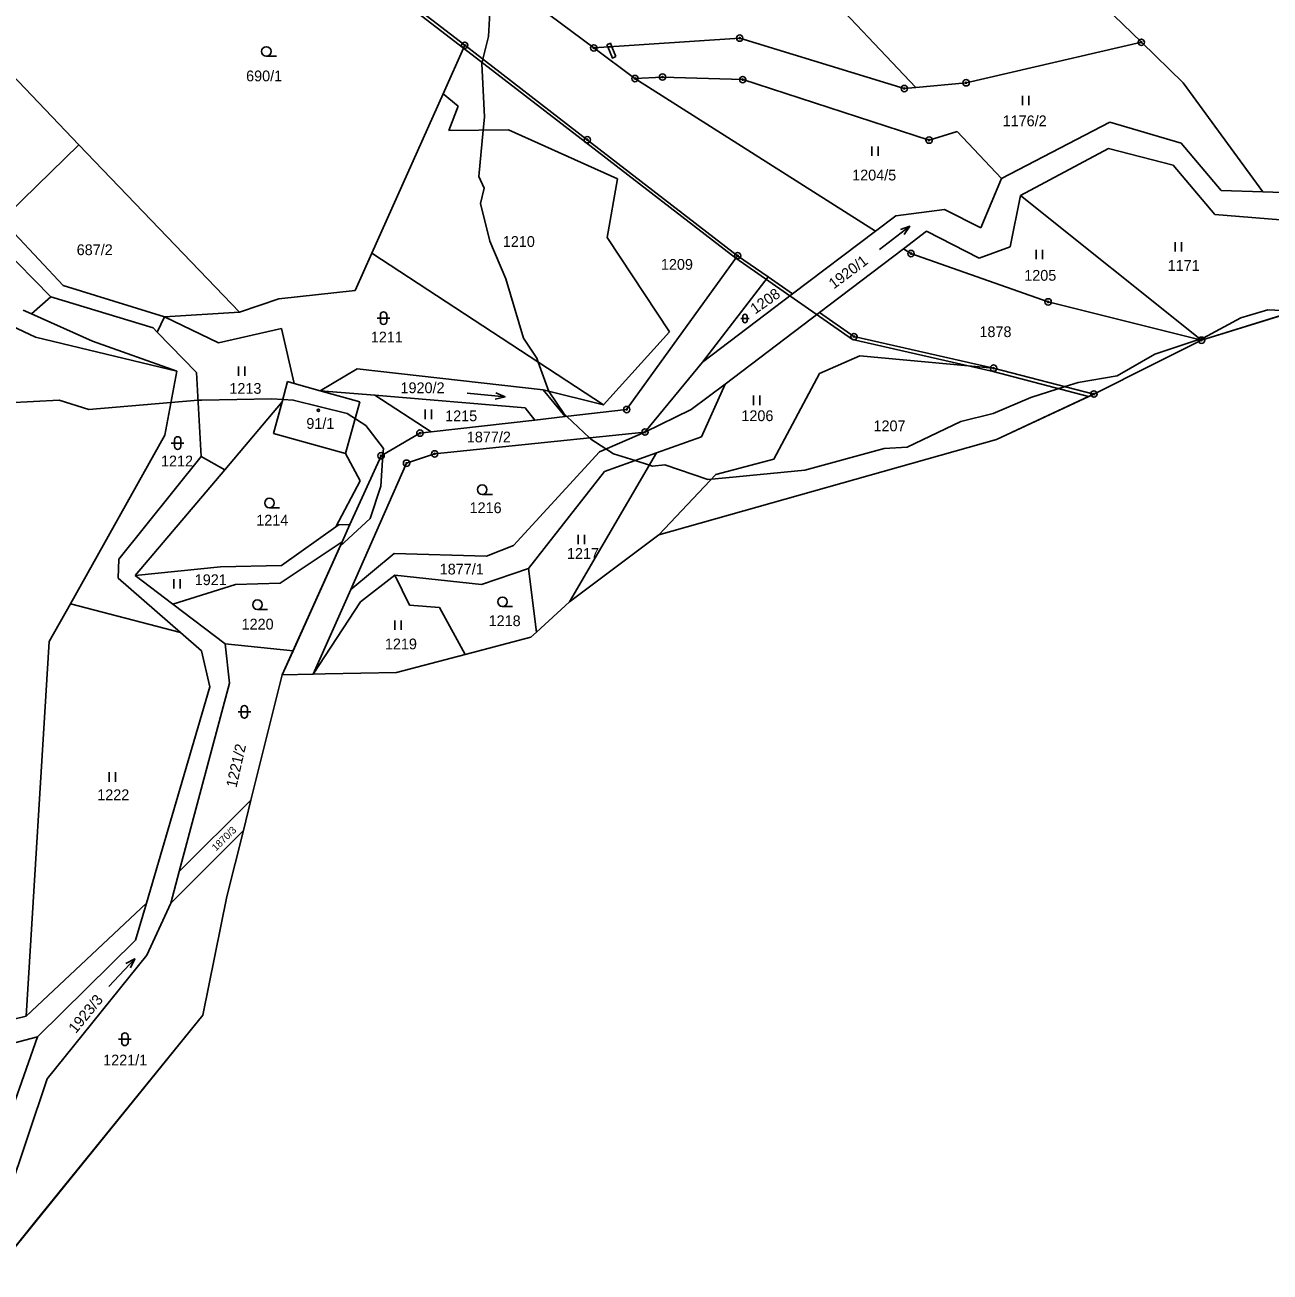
# Model space of a CAD drawing. Extents: x -445050 to -440454, y -1134563 to -1129741.
# Drawn here: x -441360.7 to -441164.1, y -1132219.4 to -1132022.5 of the extents above; entities that cross this region are included whole.
import ezdxf

# ---------------------------------------------------------------- set-up
doc = ezdxf.new("R2010")
doc.units = 0
for name, color, linetype in [('Vrstva 1', 7, 'Continuous'), ('Vrstva 13', 7, 'Continuous'), ('Vrstva 16', 7, 'Continuous'), ('Vrstva 18', 7, 'Continuous'), ('Vrstva 19', 7, 'Continuous'), ('Vrstva 24', 7, 'Continuous'), ('Vrstva 25', 7, 'Continuous'), ('Vrstva 3', 7, 'Continuous'), ('Vrstva 30', 7, 'Continuous'), ('Vrstva 37', 7, 'Continuous'), ('Vrstva 4', 7, 'Continuous'), ('Vrstva 5', 7, 'Continuous'), ('Vrstva 52', 7, 'Continuous')]:
    doc.layers.add(name, color=color, linetype=linetype)

msp = doc.modelspace()

# ---------------------------------------------------------------- linework, layer by layer
at = {"layer": 'Vrstva 1'}
for points in [[(-441291.24, -1132025.75), (-441326.34, -1131998.71)], [(-441210.7, -1131999.85), (-441184.4, -1132025.27)], [(-441298.88, -1132005.29), (-441270.86, -1132026.16)], [(-441352.15, -1132041.44), (-441384.04, -1132008.03)], [(-441220.04, -1132032.4), (-441235.94, -1132015.52)], [(-441247.82, -1132024.61), (-441270.86, -1132026.16)], [(-441221.84, -1132032.57), (-441247.82, -1132024.61)], [(-441184.4, -1132025.27), (-441212.08, -1132031.67)], [(-441184.4, -1132025.27), (-441177.79, -1132031.66)], [(-441291.24, -1132025.75), (-441294.66, -1132033.41)], [(-441271.89, -1132040.66), (-441291.24, -1132025.75)], [(-441270.86, -1132026.16), (-441264.37, -1132030.99)], [(-441260.01, -1132030.76), (-441264.37, -1132030.99)], [(-441226.36, -1132055.08), (-441264.37, -1132030.99)], [(-441247.35, -1132031.16), (-441260.01, -1132030.76)], [(-441217.92, -1132040.71), (-441247.35, -1132031.16)], [(-441220.04, -1132032.4), (-441221.84, -1132032.57)], [(-441212.08, -1132031.67), (-441220.04, -1132032.4)], [(-441177.79, -1132031.66), (-441165.23, -1132048.88)], [(-441294.66, -1132033.41), (-441305.89, -1132058.55)], [(-441292.29, -1132035.33), (-441294.66, -1132033.41)], [(-441292.29, -1132035.33), (-441293.75, -1132039.22)], [(-441293.75, -1132039.22), (-441284.35, -1132039.08)], [(-441284.35, -1132039.08), (-441267.12, -1132046.83)], [(-441206.5, -1132046.78), (-441189.36, -1132037.9)], [(-441189.36, -1132037.9), (-441178.1, -1132041.19)], [(-441248.16, -1132058.96), (-441271.89, -1132040.66)], [(-441213.49, -1132039.36), (-441217.92, -1132040.71)], [(-441206.5, -1132046.78), (-441213.49, -1132039.36)], [(-441178.1, -1132041.19), (-441171.82, -1132048.67)], [(-441365.54, -1132054.44), (-441352.15, -1132041.44)], [(-441326.78, -1132067.85), (-441352.15, -1132041.44)], [(-441189.57, -1132042.04), (-441203.49, -1132049.43)], [(-441179.36, -1132044.66), (-441189.57, -1132042.04)], [(-441172.78, -1132052.44), (-441179.36, -1132044.66)], [(-441267.12, -1132046.83), (-441268.74, -1132056.09)], [(-441209.73, -1132054.57), (-441206.5, -1132046.78)], [(-441171.82, -1132048.67), (-441165.23, -1132048.88)], [(-441165.23, -1132048.88), (-441150.88, -1132049.33)], [(-441203.49, -1132049.43), (-441205.12, -1132057.55)], [(-441203.49, -1132049.43), (-441174.91, -1132072.3)], [(-441223.15, -1132052.65), (-441226.36, -1132055.08)], [(-441215.51, -1132051.64), (-441223.15, -1132052.65)], [(-441215.51, -1132051.64), (-441209.73, -1132054.57)], [(-441160.51, -1132053.45), (-441172.78, -1132052.44)], [(-441362.34, -1132055.46), (-441354.65, -1132063.67)], [(-441268.74, -1132056.09), (-441258.93, -1132070.97)], [(-441226.36, -1132055.08), (-441239.47, -1132065)], [(-441218.31, -1132055.1), (-441221.96, -1132057.87)], [(-441210.04, -1132059.35), (-441218.31, -1132055.1)], [(-441356.58, -1132065.43), (-441364.45, -1132057.43)], [(-441305.89, -1132058.55), (-441308.52, -1132064.43)], [(-441305.89, -1132058.55), (-441269.35, -1132082.5)], [(-441248.16, -1132058.96), (-441265.68, -1132083.24)], [(-441248.16, -1132058.96), (-441243.34, -1132062.31)], [(-441221.96, -1132057.87), (-441235.25, -1132067.94)], [(-441220.78, -1132058.62), (-441221.96, -1132057.87)], [(-441220.78, -1132058.62), (-441199.13, -1132066.25)], [(-441205.12, -1132057.55), (-441210.04, -1132059.35)], [(-441243.34, -1132062.31), (-441253.7, -1132075.78)], [(-441243.34, -1132062.31), (-441239.47, -1132065)], [(-441354.65, -1132063.67), (-441338.63, -1132068.63)], [(-441320.62, -1132065.77), (-441308.52, -1132064.43)], [(-441359.01, -1132071.81), (-441372.54, -1132065.44)], [(-441356.58, -1132065.43), (-441359.65, -1132068.15)], [(-441340.45, -1132070.35), (-441356.58, -1132065.43)], [(-441326.78, -1132067.85), (-441320.62, -1132065.77)], [(-441239.47, -1132065), (-441253.7, -1132075.78)], [(-441199.13, -1132066.25), (-441174.91, -1132072.3)], [(-441360.94, -1132067.57), (-441359.65, -1132068.15)], [(-441359.65, -1132068.15), (-441350.01, -1132072.43)], [(-441338.63, -1132068.63), (-441339.81, -1132071.01)], [(-441338.63, -1132068.63), (-441326.78, -1132067.85)], [(-441338.63, -1132068.63), (-441330.14, -1132072.69)], [(-441250.14, -1132079.22), (-441235.25, -1132067.94)], [(-441235.25, -1132067.94), (-441229.78, -1132071.73)], [(-441339.81, -1132071.01), (-441340.45, -1132070.35)], [(-441330.14, -1132072.69), (-441320.19, -1132070.43)], [(-441320.19, -1132070.43), (-441318.15, -1132079.13)], [(-441336.69, -1132077.19), (-441359.01, -1132071.81)], [(-441350.01, -1132072.43), (-441336.69, -1132077.19)], [(-441333.57, -1132077.39), (-441339.81, -1132071.01)], [(-441258.93, -1132070.97), (-441269.35, -1132082.5)], [(-441207.74, -1132076.71), (-441229.78, -1132071.73)], [(-441253.7, -1132075.78), (-441262.78, -1132086.8)], [(-441228.86, -1132074.76), (-441235.21, -1132077.55)], [(-441228.86, -1132074.76), (-441207.74, -1132076.71)], [(-441338.61, -1132087.31), (-441336.69, -1132077.19)], [(-441332.87, -1132090.68), (-441333.57, -1132077.39)], [(-441308.23, -1132076.8), (-441314.05, -1132080.27)], [(-441278.87, -1132080.15), (-441308.23, -1132076.8)], [(-441235.21, -1132077.55), (-441242.45, -1132091.08)], [(-441191.9, -1132080.8), (-441207.74, -1132076.71)], [(-441320.09, -1132082.04), (-441319.21, -1132078.84)], [(-441318.15, -1132079.13), (-441319.21, -1132078.84)], [(-441318.15, -1132079.13), (-441314.05, -1132080.27)], [(-441305.43, -1132081), (-441314.05, -1132080.27)], [(-441275.37, -1132084.35), (-441278.87, -1132080.15)], [(-441269.35, -1132082.5), (-441278.87, -1132080.15)], [(-441255.47, -1132083.25), (-441250.14, -1132079.22)], [(-441253.88, -1132087.57), (-441250.14, -1132079.22)], [(-441320.09, -1132082.04), (-441329.14, -1132092.75)], [(-441321.46, -1132087.04), (-441320.09, -1132082.04)], [(-441305.43, -1132081), (-441296.52, -1132086.76)], [(-441305.43, -1132081), (-441281.71, -1132082.99)], [(-441280.17, -1132084.9), (-441281.71, -1132082.99)], [(-441280.17, -1132084.9), (-441275.37, -1132084.35)], [(-441265.68, -1132083.24), (-441275.37, -1132084.35)], [(-441262.78, -1132086.8), (-441255.47, -1132083.25)], [(-441280.17, -1132084.9), (-441296.52, -1132086.76)], [(-441353.5, -1132113.9), (-441338.61, -1132087.31)], [(-441321.46, -1132087.04), (-441310.08, -1132090.16)], [(-441298.32, -1132086.97), (-441304.45, -1132090.55)], [(-441296.52, -1132086.76), (-441298.32, -1132086.97)], [(-441262.78, -1132086.8), (-441296, -1132090.24)], [(-441262.78, -1132086.8), (-441269.96, -1132089.9)], [(-441260.97, -1132090.1), (-441253.88, -1132087.57)], [(-441310.08, -1132090.16), (-441307.75, -1132094.51)], [(-441296, -1132090.24), (-441300.43, -1132091.71)], [(-441269.96, -1132089.9), (-441283.54, -1132104.69)], [(-441260.97, -1132090.1), (-441274.7, -1132113.6)], [(-441269.18, -1132093.02), (-441260.97, -1132090.1)], [(-441345.85, -1132106.84), (-441332.87, -1132090.68)], [(-441332.87, -1132090.68), (-441329.14, -1132092.75)], [(-441304.45, -1132090.55), (-441309.39, -1132101.41)], [(-441300.43, -1132091.71), (-441309.25, -1132111.64)], [(-441242.45, -1132091.08), (-441251.58, -1132093.51)], [(-441343.28, -1132109.46), (-441329.14, -1132092.75)], [(-441281.19, -1132108.35), (-441269.18, -1132093.02)], [(-441251.58, -1132093.51), (-441260.6, -1132103)], [(-441307.75, -1132094.51), (-441311.62, -1132101.77)], [(-441311.62, -1132101.77), (-441320.17, -1132107.84)], [(-441311.14, -1132101.43), (-441311.62, -1132101.77)], [(-441309.39, -1132101.41), (-441311.14, -1132101.43)], [(-441310.61, -1132104.13), (-441309.39, -1132101.41)], [(-441320.37, -1132110.66), (-441310.61, -1132104.13)], [(-441318.34, -1132121.32), (-441310.61, -1132104.13)], [(-441302.41, -1132105.99), (-441309.25, -1132111.64)], [(-441287.78, -1132106.37), (-441302.41, -1132105.99)], [(-441283.54, -1132104.69), (-441287.78, -1132106.37)], [(-441345.96, -1132109.84), (-441345.85, -1132106.84)], [(-441343.28, -1132109.46), (-441329.81, -1132108.09)], [(-441329.81, -1132108.09), (-441320.17, -1132107.84)], [(-441345.96, -1132109.84), (-441336.12, -1132118.45)], [(-441343.28, -1132109.46), (-441337.32, -1132113.99)], [(-441307.68, -1132113.61), (-441302.3, -1132109.4)], [(-441302.3, -1132109.4), (-441288.59, -1132110.84)], [(-441302.3, -1132109.4), (-441299.94, -1132114.12)], [(-441288.59, -1132110.84), (-441281.19, -1132108.35)], [(-441281.19, -1132108.35), (-441279.9, -1132118.37)], [(-441337.32, -1132113.99), (-441327.45, -1132110.86)], [(-441327.45, -1132110.86), (-441320.37, -1132110.66)], [(-441309.25, -1132111.64), (-441315.17, -1132125.03)], [(-441356.85, -1132119.87), (-441353.5, -1132113.9)], [(-441353.5, -1132113.9), (-441336.12, -1132118.45)], [(-441337.32, -1132113.99), (-441329.09, -1132120.25)], [(-441307.68, -1132113.61), (-441315.17, -1132125.03)], [(-441299.94, -1132114.12), (-441295.25, -1132114.5)], [(-441295.25, -1132114.5), (-441291.17, -1132121.91)], [(-441360.5, -1132179.02), (-441356.85, -1132119.87)], [(-441336.12, -1132118.45), (-441332.81, -1132121.34)], [(-441331.47, -1132127.01), (-441332.81, -1132121.34)], [(-441329.09, -1132120.25), (-441318.34, -1132121.32)], [(-441329.09, -1132120.25), (-441328.39, -1132126.44)], [(-441320.06, -1132125.14), (-441318.34, -1132121.32)], [(-441331.47, -1132127.01), (-441341.48, -1132161.19)], [(-441328.39, -1132126.44), (-441336.32, -1132156.15)], [(-441336.32, -1132156.15), (-441325, -1132144.92)], [(-441337.66, -1132161.15), (-441326.19, -1132149.68)], [(-441336.32, -1132156.15), (-441337.66, -1132161.15)], [(-441360.5, -1132179.02), (-441341.48, -1132161.19)], [(-441341.48, -1132161.19), (-441343.2, -1132167)], [(-441341.46, -1132169.4), (-441337.66, -1132161.15)], [(-441358.69, -1132182.28), (-441343.2, -1132167)], [(-441357.15, -1132188.89), (-441341.46, -1132169.4)], [(-441383.77, -1132184.63), (-441360.5, -1132179.02)], [(-441358.69, -1132182.28), (-441369.76, -1132185.17)], [(-441366.23, -1132203.57), (-441358.69, -1132182.28)], [(-441363.31, -1132207.28), (-441357.15, -1132188.89)]]:
    msp.add_lwpolyline(points, dxfattribs=at)
at = {"layer": 'Vrstva 13'}
for points in [[(-441157.66, -1132066.94), (-441174.91, -1132072.3)], [(-441174.91, -1132072.3), (-441182.51, -1132076.1)], [(-441191.9, -1132080.8), (-441182.51, -1132076.1)], [(-441191.9, -1132080.8), (-441207.3, -1132087.96)], [(-441260.6, -1132103), (-441207.3, -1132087.96)], [(-441274.7, -1132113.6), (-441260.6, -1132103)], [(-441279.9, -1132118.37), (-441274.7, -1132113.6)], [(-441291.17, -1132121.91), (-441280.8, -1132119.2)], [(-441280.8, -1132119.2), (-441279.9, -1132118.37)], [(-441302, -1132124.75), (-441291.17, -1132121.91)], [(-441320.06, -1132125.14), (-441325, -1132144.92)], [(-441315.17, -1132125.03), (-441320.06, -1132125.14)], [(-441315.17, -1132125.03), (-441313.3, -1132124.99)], [(-441313.3, -1132124.99), (-441302, -1132124.75)], [(-441325, -1132144.92), (-441326.19, -1132149.68)], [(-441326.19, -1132149.68), (-441328.8, -1132160.1)], [(-441328.8, -1132160.1), (-441332.58, -1132178.83)], [(-441365.51, -1132219.4), (-441332.58, -1132178.83)]]:
    msp.add_lwpolyline(points, dxfattribs=at)
at = {"layer": 'Vrstva 24'}
for centre, radius in [((-441291.24, -1132025.75), 0.5), ((-441247.82, -1132024.61), 0.5), ((-441247.82, -1132024.61), 0.1), ((-441184.4, -1132025.27), 0.5), ((-441184.4, -1132025.27), 0.1), ((-441291.24, -1132025.75), 0.1), ((-441270.86, -1132026.16), 0.5), ((-441270.86, -1132026.16), 0.1), ((-441264.37, -1132030.99), 0.5), ((-441264.37, -1132030.99), 0.1), ((-441260.01, -1132030.76), 0.5), ((-441260.01, -1132030.76), 0.1), ((-441247.35, -1132031.16), 0.5), ((-441247.35, -1132031.16), 0.1), ((-441212.08, -1132031.67), 0.5), ((-441221.84, -1132032.57), 0.5), ((-441221.84, -1132032.57), 0.1), ((-441212.08, -1132031.67), 0.1), ((-441271.89, -1132040.66), 0.5), ((-441271.89, -1132040.66), 0.1), ((-441217.92, -1132040.71), 0.5), ((-441217.92, -1132040.71), 0.1), ((-441248.16, -1132058.96), 0.5), ((-441248.16, -1132058.96), 0.1), ((-441220.78, -1132058.62), 0.5), ((-441220.78, -1132058.62), 0.1), ((-441199.13, -1132066.25), 0.5), ((-441199.13, -1132066.25), 0.1), ((-441229.78, -1132071.73), 0.5), ((-441229.78, -1132071.73), 0.1), ((-441174.91, -1132072.3), 0.5), ((-441174.91, -1132072.3), 0.1), ((-441207.74, -1132076.71), 0.5), ((-441207.74, -1132076.71), 0.1), ((-441191.9, -1132080.8), 0.5), ((-441191.9, -1132080.8), 0.1), ((-441265.68, -1132083.24), 0.5), ((-441265.68, -1132083.24), 0.1), ((-441298.32, -1132086.97), 0.5), ((-441262.78, -1132086.8), 0.5), ((-441298.32, -1132086.97), 0.1), ((-441262.78, -1132086.8), 0.1), ((-441304.45, -1132090.55), 0.5), ((-441304.45, -1132090.55), 0.1), ((-441296, -1132090.24), 0.5), ((-441296, -1132090.24), 0.1), ((-441300.43, -1132091.71), 0.5), ((-441300.43, -1132091.71), 0.1)]:
    msp.add_circle(centre, radius, dxfattribs=at)
at = {"layer": 'Vrstva 25'}
for p, q in [((-441322.57, -1132027.47), (-441320.97, -1132027.47)), ((-441203.2, -1132035.2), (-441203.2, -1132033.7)), ((-441202.2, -1132035.2), (-441202.2, -1132033.7)), ((-441226.95, -1132043.22), (-441226.95, -1132041.72)), ((-441225.95, -1132043.22), (-441225.95, -1132041.72)), ((-441179.06, -1132058.32), (-441179.06, -1132056.82)), ((-441178.06, -1132058.32), (-441178.06, -1132056.82)), ((-441200.99, -1132059.52), (-441200.99, -1132058.02)), ((-441199.99, -1132059.52), (-441199.99, -1132058.02)), ((-441305.06, -1132068.81), (-441303.06, -1132068.81)), ((-441304.56, -1132069.31), (-441304.56, -1132068.31)), ((-441303.56, -1132068.31), (-441303.56, -1132069.31)), ((-441247.34, -1132069.22), (-441247.34, -1132068.54)), ((-441246.67, -1132068.54), (-441246.67, -1132069.22)), ((-441247.67, -1132068.88), (-441246.33, -1132068.88)), ((-441326.95, -1132077.94), (-441326.95, -1132076.44)), ((-441325.95, -1132077.94), (-441325.95, -1132076.44)), ((-441245.65, -1132082.53), (-441245.65, -1132081.03)), ((-441244.65, -1132082.53), (-441244.65, -1132081.03)), ((-441297.51, -1132084.75), (-441297.51, -1132083.25)), ((-441296.51, -1132084.75), (-441296.51, -1132083.25)), ((-441337.07, -1132089.03), (-441337.07, -1132088.03)), ((-441336.07, -1132088.03), (-441336.07, -1132089.03)), ((-441337.57, -1132088.53), (-441335.57, -1132088.53)), ((-441288.48, -1132096.64), (-441286.88, -1132096.64)), ((-441322.08, -1132098.75), (-441320.48, -1132098.75)), ((-441273.32, -1132104.5), (-441273.32, -1132103)), ((-441272.32, -1132104.5), (-441272.32, -1132103)), ((-441337.19, -1132111.5), (-441337.19, -1132110)), ((-441336.19, -1132111.5), (-441336.19, -1132110)), ((-441323.97, -1132114.8), (-441322.37, -1132114.8)), ((-441285.28, -1132114.34), (-441283.68, -1132114.34)), ((-441302.3, -1132118.03), (-441302.3, -1132116.53)), ((-441301.3, -1132118.03), (-441301.3, -1132116.53)), ((-441327.04, -1132130.97), (-441325.04, -1132130.97)), ((-441326.54, -1132131.47), (-441326.54, -1132130.47)), ((-441325.54, -1132130.47), (-441325.54, -1132131.47)), ((-441347.41, -1132141.99), (-441347.41, -1132140.49)), ((-441346.41, -1132141.99), (-441346.41, -1132140.49)), ((-441345.9, -1132182.65), (-441343.9, -1132182.65)), ((-441345.4, -1132183.15), (-441345.4, -1132182.15)), ((-441344.4, -1132182.15), (-441344.4, -1132183.15))]:
    msp.add_line(p, q, dxfattribs=at)
for points in [[(-441225.73, -1132057.96), (-441220.97, -1132054.32), (-441222.46, -1132054.83)], [(-441220.97, -1132054.32), (-441221.85, -1132055.63)], [(-441290.86, -1132080.67), (-441284.88, -1132081.25), (-441286.33, -1132080.61)], [(-441284.88, -1132081.25), (-441286.43, -1132081.6)], [(-441347.44, -1132174.32), (-441343.34, -1132169.94), (-441344.73, -1132170.69)], [(-441343.34, -1132169.94), (-441344, -1132171.38)]]:
    msp.add_lwpolyline(points, dxfattribs=at)
for centre, radius in [((-441322.57, -1132026.72), 0.75), ((-441314.35, -1132083.36), 0.175), ((-441288.48, -1132095.89), 0.75), ((-441322.08, -1132098), 0.75), ((-441323.97, -1132114.05), 0.75), ((-441285.28, -1132113.59), 0.75)]:
    msp.add_circle(centre, radius, dxfattribs=at)
for centre, radius, start, end in [((-441304.06, -1132068.31), 0.5, 0, 180), ((-441247, -1132068.54), 0.335, 0, 180), ((-441304.06, -1132069.31), 0.5, 180, 0), ((-441247, -1132069.22), 0.335, 180, 0), ((-441336.57, -1132088.03), 0.5, 0, 180), ((-441336.57, -1132089.03), 0.5, 180, 0), ((-441326.04, -1132130.47), 0.5, 0, 180), ((-441326.04, -1132131.47), 0.5, 180, 0), ((-441344.9, -1132182.15), 0.5, 0, 180), ((-441344.9, -1132183.15), 0.5, 180, 0)]:
    msp.add_arc(centre, radius, start, end, dxfattribs=at)
at = {"layer": 'Vrstva 3'}
for points in [[(-441320.09, -1132082.04), (-441319.21, -1132078.84)], [(-441318.15, -1132079.13), (-441319.21, -1132078.84)], [(-441318.15, -1132079.13), (-441314.05, -1132080.27)], [(-441314.05, -1132080.27), (-441307.79, -1132082.02)], [(-441321.46, -1132087.04), (-441320.09, -1132082.04)], [(-441307.79, -1132082.02), (-441310.08, -1132090.16)], [(-441321.46, -1132087.04), (-441310.08, -1132090.16)]]:
    msp.add_lwpolyline(points, dxfattribs=at)
at = {"layer": 'Vrstva 30'}
for points in [[(-441268.79, -1132025.65), (-441268.24, -1132025.42), (-441268.01, -1132025.97), (-441268.64, -1132026.01), (-441268.79, -1132025.65)], [(-441267.36, -1132027.52), (-441267.92, -1132027.76), (-441268.64, -1132026.01), (-441268.01, -1132025.97), (-441267.36, -1132027.52)]]:
    msp.add_lwpolyline(points, dxfattribs=at)
at = {"layer": 'Vrstva 37'}
msp.add_circle((-441314.35, -1132083.36), 0.175, dxfattribs=at)
at = {"layer": 'Vrstva 4'}
for points in [[(-441314.05, -1132080.27), (-441307.79, -1132082.02)], [(-441307.79, -1132082.02), (-441310.08, -1132090.16)]]:
    msp.add_lwpolyline(points, dxfattribs=at)
at = {"layer": 'Vrstva 5'}
for points in [[(-441326.64, -1131999.11), (-441291.45, -1132026.22)], [(-441291.45, -1132026.22), (-441272.19, -1132041.06)], [(-441272.19, -1132041.06), (-441248.45, -1132059.37)], [(-441248.45, -1132059.37), (-441230, -1132072.17)], [(-441230, -1132072.17), (-441207.79, -1132077.26)], [(-441207.79, -1132077.26), (-441192.73, -1132081.18)]]:
    msp.add_lwpolyline(points, dxfattribs=at)
at = {"layer": 'Vrstva 52'}
for points in [[(-441287.07, -1132016.71), (-441287.5, -1132024.36), (-441288.39, -1132027.94), (-441288.56, -1132028.61), (-441288.14, -1132037.11), (-441288.32, -1132039.14), (-441288.99, -1132046.46), (-441288.18, -1132048.28), (-441288.77, -1132050.72), (-441287.28, -1132056.67), (-441284.73, -1132062.62), (-441281.97, -1132071.97), (-441279.85, -1132075.16), (-441279.63, -1132075.76), (-441277.97, -1132080.37), (-441277.93, -1132080.47), (-441275.6, -1132083.87), (-441275.12, -1132084.32), (-441271.56, -1132087.71), (-441271.34, -1132087.91), (-441268.95, -1132089.46), (-441267.73, -1132090.25), (-441264.34, -1132091.3), (-441262.08, -1132092), (-441261.57, -1132092.16), (-441259.66, -1132091.95), (-441252.85, -1132094.29), (-441252.26, -1132094.23), (-441250, -1132094.01), (-441237.55, -1132092.8), (-441225.01, -1132089.4), (-441221.4, -1132089.19), (-441212.9, -1132085.15), (-441207.8, -1132083.87), (-441201.85, -1132081.32), (-441196.45, -1132079.63), (-441194.41, -1132078.98), (-441188.24, -1132077.92), (-441182.29, -1132074.52), (-441175.32, -1132072.2), (-441175.12, -1132072.13), (-441174.64, -1132071.97), (-441168.69, -1132068.78), (-441164.44, -1132067.51), (-441160.07, -1132067.69)], [(-441160.07, -1132067.69), (-441174.91, -1132072.3), (-441182.51, -1132076.1), (-441184.41, -1132077.05), (-441190.24, -1132079.97), (-441191.9, -1132080.8), (-441192.73, -1132081.18), (-441207.3, -1132087.96), (-441260.6, -1132103), (-441274.7, -1132113.6), (-441279.9, -1132118.37), (-441280.8, -1132119.2), (-441291.17, -1132121.91), (-441302, -1132124.75), (-441313.3, -1132124.99), (-441315.17, -1132125.03), (-441320.06, -1132125.14)], [(-441363.37, -1132082.17), (-441355.3, -1132081.75), (-441350.62, -1132083.23), (-441337.63, -1132082.15), (-441333.34, -1132081.79), (-441332.77, -1132081.75), (-441321.72, -1132081.53), (-441319.98, -1132081.64), (-441318.32, -1132081.75), (-441309.81, -1132083.87), (-441306.84, -1132085.78), (-441304.08, -1132089.4), (-441304.15, -1132090.37), (-441304.5, -1132095.35), (-441306.2, -1132100.45), (-441310.91, -1132104.8), (-441320.06, -1132125.14)], [(-441320.06, -1132125.14), (-441325, -1132144.92), (-441326.19, -1132149.68), (-441328.8, -1132160.1), (-441332.58, -1132178.83), (-441358.9, -1132211.25), (-441365.51, -1132219.4)]]:
    msp.add_lwpolyline(points, dxfattribs=at)

# ---------------------------------------------------------------- texts
at = {"layer": 'Vrstva 16'}
msp.add_text('1920/1', height=1.7, rotation=36.9571, dxfattribs=at).set_placement((-441232.97, -1132064.3))
at = {"layer": 'Vrstva 18'}
for s, p in [('690/1', (-441325.76, -1132031.43)), ('1176/2', (-441206.31, -1132038.52)), ('1204/5', (-441230.07, -1132047.08)), ('1210', (-441285.23, -1132057.57)), ('687/2', (-441352.51, -1132058.87)), ('1209', (-441260.27, -1132061.18)), ('1171', (-441180.26, -1132061.36)), ('1205', (-441202.9, -1132062.91)), ('1878', (-441209.97, -1132071.81)), ('1211', (-441306.07, -1132072.65)), ('1213', (-441328.4, -1132080.76)), ('1920/2', (-441301.38, -1132080.66)), ('1215', (-441294.33, -1132085.09)), ('1206', (-441247.56, -1132085.07)), ('1207', (-441226.7, -1132086.67)), ('1877/2', (-441290.91, -1132088.43)), ('1212', (-441339.2, -1132092.22)), ('1216', (-441290.48, -1132099.6)), ('1214', (-441324.16, -1132101.56)), ('1217', (-441275.1, -1132106.82)), ('1877/1', (-441295.19, -1132109.28)), ('1921', (-441333.87, -1132110.96)), ('1218', (-441287.47, -1132117.44)), ('1220', (-441326.48, -1132117.97)), ('1219', (-441303.85, -1132121.1)), ('1222', (-441349.27, -1132144.91)), ('1221/1', (-441348.33, -1132186.78))]:
    msp.add_text(s, height=1.7, dxfattribs=at).set_placement(p)
for s, height, rotation, p in [('1208', 1.7, 34.9713, (-441245.39, -1132068.26)), ('1221/2', 1.7, 77.2623, (-441327.29, -1132143.04)), ('1870/3', 1.14, 44.4491, (-441330.52, -1132153.02)), ('1923/3', 1.7, 50.6151, (-441352.65, -1132181.84))]:
    msp.add_text(s, height=height, rotation=rotation, dxfattribs=at).set_placement(p)
at = {"layer": 'Vrstva 19'}
msp.add_text('91/1', height=1.7, dxfattribs=at).set_placement((-441316.25, -1132086.29))

doc.saveas('drawing.dxf')
